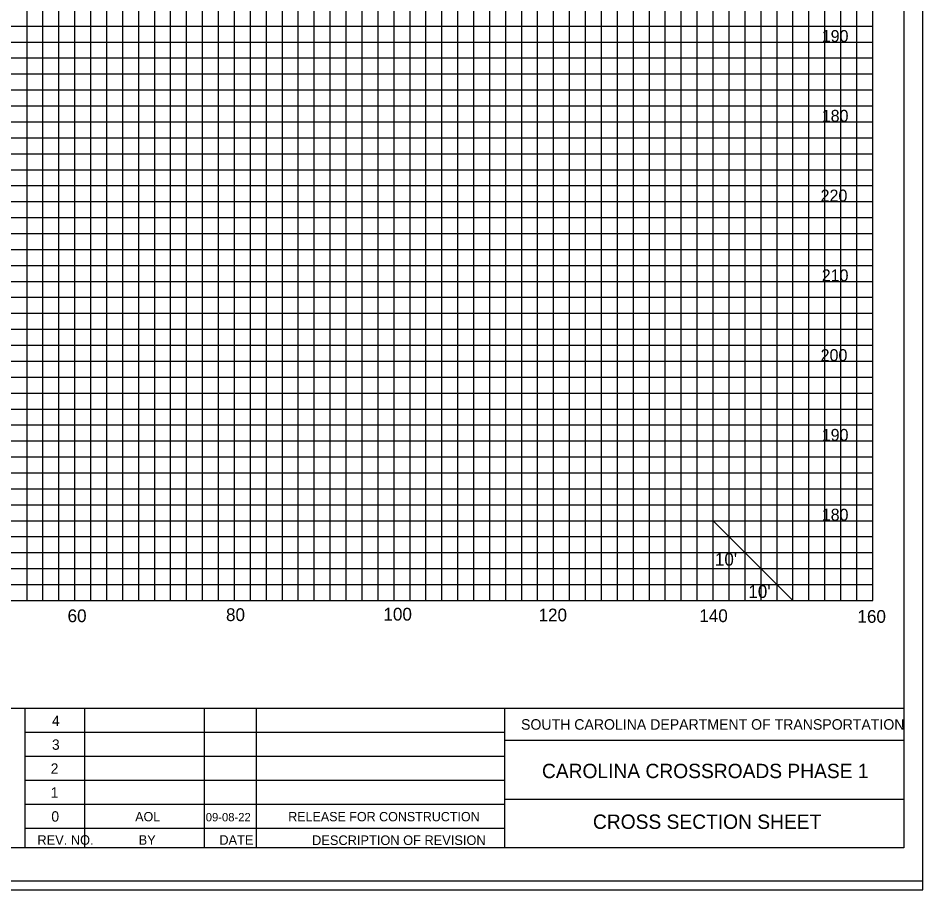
# Model space of a CAD drawing. Extents: x 967 to 1326, y 964 to 2584.
# Drawn here: x 1212.9 to 1326.3, y 2083.7 to 2193 of the extents above; entities that cross this region are included whole.
import ezdxf

# ---------------------------------------------------------------- set-up
doc = ezdxf.new("R2010")
doc.units = 0
for name, color, linetype in [('Default', 7, 'Continuous'), ('RD_SHT_Bndy', 7, 'Continuous'), ('RD_SHT_IplotShp', 7, 'Continuous'), ('RD_SHT_Misc1', 7, 'Continuous'), ('RD_SHT_MjGrid', 7, 'Continuous'), ('RD_SHT_MnGrid', 7, 'Continuous'), ('RD_SHT_TX', 7, 'Continuous'), ('RD_Sketch1', 7, 'Continuous')]:
    doc.layers.add(name, color=color, linetype=linetype)

msp = doc.modelspace()

# ---------------------------------------------------------------- linework, layer by layer
at = {"layer": 'RD_SHT_Bndy'}
for p, q in [((1323.89, 2298.46), (1323.89, 2088.98)), ((996.11, 2106.49), (1323.89, 2106.49)), ((1213.76, 2088.94), (1213.76, 2106.49)), ((1221.26, 2088.95), (1221.26, 2106.48)), ((1236.26, 2088.95), (1236.26, 2106.48)), ((1242.76, 2088.95), (1242.76, 2106.48)), ((1273.88, 2088.98), (1273.88, 2106.49)), ((1213.76, 2103.48), (1273.88, 2103.48)), ((1323.93, 2102.43), (1273.88, 2102.43)), ((1213.76, 2100.48), (1273.88, 2100.48)), ((1213.76, 2097.48), (1273.88, 2097.48)), ((1323.89, 2095.04), (1273.88, 2095.04)), ((1213.76, 2094.48), (1273.88, 2094.48)), ((1213.76, 2091.48), (1273.88, 2091.48)), ((1323.89, 2088.98), (996.11, 2088.98))]:
    msp.add_line(p, q, dxfattribs=at)
at = {"layer": 'RD_SHT_IplotShp'}
for points in [[(967.41, 2083.72), (1326.28, 2083.72), (1326.28, 2303.72), (967.41, 2303.72)], [(988.52, 2084.84), (1326.28, 2084.84), (1326.28, 2302.6), (988.52, 2302.6)]]:
    msp.add_lwpolyline(points, close=True, dxfattribs=at)
at = {"layer": 'RD_SHT_MjGrid'}
for p, q in [((1220, 2120), (1220, 2290)), ((1230, 2120), (1230, 2290)), ((1240, 2120), (1240, 2290)), ((1250, 2120), (1250, 2290)), ((1260, 2120), (1260, 2290)), ((1270, 2120), (1270, 2290)), ((1280, 2120), (1280, 2290)), ((1290, 2120), (1290, 2290)), ((1300, 2120), (1300, 2290)), ((1310, 2120), (1310, 2290)), ((1320, 2120), (1320, 2290)), ((1000, 2190), (1320, 2190)), ((1000, 2180), (1320, 2180)), ((1000, 2170), (1320, 2170)), ((1000, 2160), (1320, 2160)), ((1000, 2150), (1320, 2150)), ((1000, 2140), (1320, 2140)), ((1000, 2130), (1320, 2130)), ((1000, 2120), (1320, 2120))]:
    msp.add_line(p, q, dxfattribs=at)
at = {"layer": 'RD_SHT_MnGrid'}
for p, q in [((1214, 2120), (1214, 2290)), ((1216, 2120), (1216, 2290)), ((1218, 2120), (1218, 2290)), ((1222, 2120), (1222, 2290)), ((1224, 2120), (1224, 2290)), ((1226, 2120), (1226, 2290)), ((1228, 2120), (1228, 2290)), ((1232, 2120), (1232, 2290)), ((1234, 2120), (1234, 2290)), ((1236, 2120), (1236, 2290)), ((1238, 2120), (1238, 2290)), ((1242, 2120), (1242, 2290)), ((1244, 2120), (1244, 2290)), ((1246, 2120), (1246, 2290)), ((1248, 2120), (1248, 2290)), ((1252, 2120), (1252, 2290)), ((1254, 2120), (1254, 2290)), ((1256, 2120), (1256, 2290)), ((1258, 2120), (1258, 2290)), ((1262, 2120), (1262, 2290)), ((1264, 2120), (1264, 2290)), ((1266, 2120), (1266, 2290)), ((1268, 2120), (1268, 2290)), ((1272, 2120), (1272, 2290)), ((1274, 2120), (1274, 2290)), ((1276, 2120), (1276, 2290)), ((1278, 2120), (1278, 2290)), ((1282, 2120), (1282, 2290)), ((1284, 2120), (1284, 2290)), ((1286, 2120), (1286, 2290)), ((1288, 2120), (1288, 2290)), ((1292, 2120), (1292, 2290)), ((1294, 2120), (1294, 2290)), ((1296, 2120), (1296, 2290)), ((1298, 2120), (1298, 2290)), ((1302, 2120), (1302, 2290)), ((1304, 2120), (1304, 2290)), ((1306, 2120), (1306, 2290)), ((1308, 2120), (1308, 2290)), ((1312, 2120), (1312, 2290)), ((1314, 2120), (1314, 2290)), ((1316, 2120), (1316, 2290)), ((1318, 2120), (1318, 2290)), ((1000, 2192), (1320, 2192)), ((1000, 2188), (1320, 2188)), ((1000, 2186), (1320, 2186)), ((1000, 2184), (1320, 2184)), ((1000, 2182), (1320, 2182)), ((1000, 2178), (1320, 2178)), ((1000, 2176), (1320, 2176)), ((1000, 2174), (1320, 2174)), ((1000, 2172), (1320, 2172)), ((1000, 2168), (1320, 2168)), ((1000, 2166), (1320, 2166)), ((1000, 2164), (1320, 2164)), ((1000, 2162), (1320, 2162)), ((1000, 2158), (1320, 2158)), ((1000, 2156), (1320, 2156)), ((1000, 2154), (1320, 2154)), ((1000, 2152), (1320, 2152)), ((1000, 2148), (1320, 2148)), ((1000, 2146), (1320, 2146)), ((1000, 2144), (1320, 2144)), ((1000, 2142), (1320, 2142)), ((1000, 2138), (1320, 2138)), ((1000, 2136), (1320, 2136)), ((1000, 2134), (1320, 2134)), ((1000, 2132), (1320, 2132)), ((1000, 2128), (1320, 2128)), ((1000, 2126), (1320, 2126)), ((1000, 2124), (1320, 2124)), ((1000, 2122), (1320, 2122))]:
    msp.add_line(p, q, dxfattribs=at)
at = {"layer": 'RD_SHT_TX'}
msp.add_line((1300, 2130), (1310, 2120), dxfattribs=at)
at = {"layer": 'RD_Sketch1'}
msp.add_lwpolyline([(967.41, 2083.72), (1326.28, 2083.72), (1326.28, 2303.72), (967.41, 2303.72)], close=True, dxfattribs=at)

# ---------------------------------------------------------------- texts
at = {"layer": 'Default'}
for s, p in [('190', (1313.61, 2190)), ('180', (1313.61, 2180)), ('220', (1313.47, 2170)), ('210', (1313.61, 2160)), ('200', (1313.47, 2150)), ('190', (1313.61, 2140)), ('180', (1313.61, 2130))]:
    msp.add_text(s, height=1.5, dxfattribs=at).set_placement(p)
at = {"layer": 'RD_SHT_Misc1'}
for s, height, p in [('AOL', 1.17, (1227.56, 2092.32)), ('RELEASE FOR CONSTRUCTION', 1.17, (1246.74, 2092.32)), ('09-08-22', 1.053, (1236.4, 2092.31))]:
    msp.add_text(s, height=height, dxfattribs=at).set_placement(p)
at = {"layer": 'RD_SHT_TX'}
for s, height, p in [("10'", 1.6, (1300.21, 2124.36)), ("10'", 1.6, (1304.4, 2120.32)), ('60', 1.6, (1219.08, 2117.28)), ('80', 1.6, (1238.94, 2117.42)), ('100', 1.6, (1258.67, 2117.48)), ('120', 1.6, (1278.11, 2117.38)), ('140', 1.6, (1298.26, 2117.29)), ('160', 1.6, (1318.08, 2117.2)), ('4', 1.3, (1217.13, 2104.28)), ('SOUTH CAROLINA DEPARTMENT OF TRANSPORTATION', 1.32, (1275.92, 2103.8)), ('3', 1.3, (1217.13, 2101.28)), ('2', 1.3, (1216.97, 2098.28)), ('1', 1.3, (1216.97, 2095.28)), ('0', 1.3, (1217.05, 2092.28)), ('REV. NO.', 1.2, (1215.3, 2089.38)), ('BY', 1.2, (1227.99, 2089.38)), ('DATE', 1.2, (1238.1, 2089.38)), ('DESCRIPTION OF REVISION', 1.2, (1249.73, 2089.35))]:
    msp.add_text(s, height=height, dxfattribs=at).set_placement(p)
for s, p in [('CAROLINA CROSSROADS PHASE 1', (1278.54, 2097.73)), ('CROSS SECTION SHEET', (1284.93, 2091.37))]:
    msp.add_text(s, height=1.8, rotation=0, dxfattribs=at).set_placement(p)

doc.saveas('drawing.dxf')
